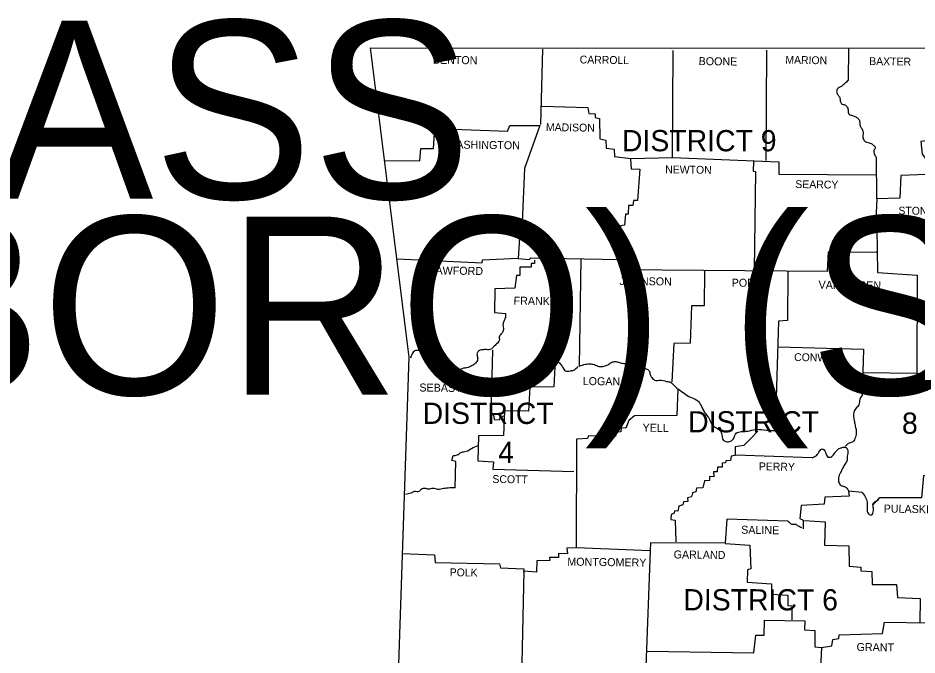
# Model space of a CAD drawing. Extents: x 309348 to 309445, y 336383 to 336484.
# Drawn here: x 309371.203 to 309375.728, y 336399.208 to 336402.416 of the extents above; entities that cross this region are included whole.
import ezdxf

# ---------------------------------------------------------------- set-up
doc = ezdxf.new("R2010")
doc.units = 0
doc.layers.add('R_Annotation', color=7, linetype='Continuous')

msp = doc.modelspace()

# ---------------------------------------------------------------- linework, layer by layer
at = {"layer": 'R_Annotation'}
msp.add_line((309375.5062, 336399.965), (309375.5401, 336399.9989), dxfattribs=at)
for points in [[(309372.9764, 336402.2658), (309374.4937, 336402.2641), (309375.8252, 336402.2663), (309377.396, 336402.29), (309378.1242, 336402.3065)], [(309372.9764, 336402.2658), (309373.1698, 336400.7078), (309373.0841, 336398.1647)], [(309373.8425, 336402.2597), (309373.8338, 336401.8801)], [(309373.8405, 336401.9729), (309374.0713, 336401.9653), (309374.0769, 336401.9353), (309374.1088, 336401.9343), (309374.1079, 336401.9156), (309374.1304, 336401.91), (309374.1322, 336401.8078), (309374.1613, 336401.8012), (309374.1631, 336401.7609), (309374.2044, 336401.7553), (309374.2063, 336401.7178), (309374.2879, 336401.7093), (309374.4981, 336401.7139), (309374.5003, 336402.2529)], [(309374.9704, 336402.2545), (309374.9673, 336401.6977)], [(309375.3832, 336402.2609), (309375.3813, 336402.1006)], [(309375.8252, 336402.2607), (309375.827, 336402.0376), (309375.811, 336402.0367), (309375.8137, 336401.8033), (309375.748, 336401.7939), (309375.7536, 336401.7311), (309375.7761, 336401.7021), (309375.7742, 336401.628), (309375.6466, 336401.6234), (309375.6418, 336401.509), (309375.5255, 336401.5053), (309375.5198, 336401.3666), (309375.5263, 336401.3553), (309375.529, 336401.1341), (309375.7298, 336401.1209), (309375.7268, 336400.6269), (309375.8863, 336400.6221), (309375.886, 336400.1197), (309375.7603, 336400.1104), (309375.7509, 336399.9998), (309375.5397, 336399.9989)], [(309373.0502, 336401.6986), (309373.2257, 336401.6976), (309373.2304, 336401.7595), (309373.2952, 336401.7594), (309373.3008, 336401.8597), (309373.6668, 336401.8464), (309373.6781, 336401.8746), (309373.8291, 336401.8754), (309373.753, 336401.658), (309373.7378, 336401.3102), (309373.7266, 336401.3093), (309373.7209, 336401.2043), (309373.7763, 336401.1996), (309373.7847, 336401.208), (309374.2323, 336401.1994), (309374.237, 336401.1497)], [(309374.286, 336401.7074), (309374.2898, 336401.6568), (309374.3329, 336401.654), (309374.3216, 336401.4965), (309374.3019, 336401.4974), (309374.2981, 336401.4721), (309374.2756, 336401.4721), (309374.2746, 336401.429), (309374.2606, 336401.4281), (309374.2558, 336401.3728), (309374.2352, 336401.37), (309374.2323, 336401.2856), (309374.2417, 336401.2791), (309374.2323, 336401.1994)], [(309374.4981, 336401.7139), (309375.0329, 336401.6911), (309375.032, 336401.6302), (309375.5227, 336401.6262)], [(309375.5255, 336401.5053), (309375.5247, 336401.7162)], [(309374.9044, 336401.694), (309374.9034, 336401.6453), (309374.9156, 336401.6425), (309374.9079, 336401.1475)], [(309374.237, 336401.1497), (309375.2785, 336401.1408), (309375.2833, 336401.2392), (309375.5253, 336401.2363)], [(309375.5225, 336401.2372), (309375.5253, 336401.24)], [(309373.1119, 336401.2037), (309373.5388, 336401.1838), (309373.5407, 336401.1988), (309373.719, 336401.2071)], [(309373.8035, 336401.1958), (309373.8035, 336401.179), (309373.7856, 336401.179), (309373.7866, 336401.1621), (309373.7293, 336401.1612), (309373.7284, 336401.119), (309373.7124, 336401.119), (309373.7039, 336401.0562), (309373.6026, 336401.0516), (309373.6016, 336400.9325), (309373.656, 336400.9288)], [(309374.0352, 336401.2032), (309374.0284, 336400.6624)], [(309374.6583, 336401.142), (309374.6572, 336400.9667), (309374.5925, 336400.9658), (309374.5868, 336400.7793), (309374.5042, 336400.7765), (309374.4947, 336400.5834)], [(309375.0786, 336401.1371), (309375.0766, 336400.8934), (309375.0316, 336400.8897), (309375.0135, 336400.3385)], [(309375.0297, 336400.7594), (309375.4585, 336400.7489), (309375.4527, 336400.5174)], [(309373.5921, 336400.7432), (309373.5826, 336400.4207), (309373.5966, 336400.417), (309373.5994, 336400.3945), (309373.6276, 336400.3926), (309373.6304, 336400.4085), (309373.6529, 336400.4123)], [(309373.9074, 336400.6924), (309373.9007, 336400.5584), (309373.7787, 336400.5575), (309373.7721, 336400.4356), (309373.6511, 336400.4385), (309373.6472, 336400.3129), (309373.5206, 336400.312), (309373.5167, 336400.1864), (309373.5965, 336400.1817), (309373.5937, 336400.1433), (309374.0009, 336400.1318)], [(309375.4537, 336400.6308), (309375.7268, 336400.6269)], [(309374.5238, 336400.5487), (309374.52, 336400.4137), (309374.306, 336400.4129), (309374.2778, 336400.3885), (309374.2619, 336400.351), (309374.2384, 336400.3529), (309374.2375, 336400.3314), (309374.2103, 336400.3286), (309374.2112, 336400.3089), (309374.0751, 336400.3127), (309374.0704, 336400.2977), (309374.0141, 336400.2959), (309374.012, 336399.7475), (309373.9651, 336399.7466), (309373.9688, 336399.7185), (309373.9238, 336399.7194), (309373.9228, 336399.6988), (309373.8787, 336399.6988), (309373.8796, 336399.6838), (309373.8139, 336399.682), (309373.813, 336399.6248), (309373.7492, 336399.6304), (309373.7386, 336399.1693)], [(309374.9262, 336400.3348), (309374.8924, 336400.2983), (309374.8558, 336400.2636), (309374.8136, 336400.2571), (309374.8136, 336400.213), (309374.7929, 336400.2102), (309374.7891, 336400.1877), (309374.7657, 336400.1858), (309374.7638, 336400.1755), (309374.7479, 336400.1746), (309374.7469, 336400.1549), (309374.7244, 336400.154), (309374.7225, 336400.1315), (309374.7037, 336400.1315), (309374.7047, 336400.1053), (309374.684, 336400.1071), (309374.6831, 336400.0865), (309374.6577, 336400.0847), (309374.6502, 336400.0509), (309374.6183, 336400.0481), (309374.6155, 336400.0294), (309374.5986, 336400.0247), (309374.5939, 336400.005), (309374.5723, 336400.0003), (309374.5742, 336399.9806), (309374.5526, 336399.9788), (309374.5488, 336399.9638), (309374.5291, 336399.9582), (309374.5244, 336399.9329), (309374.5094, 336399.9338), (309374.5047, 336399.9207), (309374.4906, 336399.916), (309374.4897, 336399.8907), (309374.5112, 336399.8869), (309374.5149, 336399.7782)], [(309373.4031, 336400.0505), (309373.406, 336400.1827), (309373.3873, 336400.1883), (309373.3929, 336400.2137)], [(309375.2011, 336400.2016), (309374.8145, 336400.2139)], [(309375.4515, 336400.0262), (309375.384, 336400.0337), (309375.3868, 336400.0084), (309375.2639, 336400.0038), (309375.2601, 336399.9672), (309375.1447, 336399.9607), (309375.1381, 336399.8951), (309375.1549, 336399.8866), (309375.1549, 336399.8435)], [(309375.078, 336399.8829), (309374.7712, 336399.8924), (309374.7627, 336399.7715), (309374.3873, 336399.7736), (309374.3854, 336399.7333)], [(309375.1615, 336399.8857), (309375.2666, 336399.8791), (309375.2628, 336399.7619), (309375.3857, 336399.7572), (309375.3875, 336399.655), (309375.4457, 336399.6503), (309375.4457, 336399.6325), (309375.5001, 336399.6287), (309375.502, 336399.5631), (309375.6258, 336399.563), (309375.6295, 336399.4983), (309375.744, 336399.4927), (309375.743, 336399.3708)], [(309374.7626, 336399.7705), (309374.8875, 336399.7612), (309374.8911, 336399.643), (309374.8752, 336399.6374), (309374.8733, 336399.5746), (309374.9962, 336399.5661), (309374.9962, 336399.5146), (309375.0778, 336399.5098), (309375.0787, 336399.4583), (309375.0984, 336399.4555), (309375.0974, 336399.3861)], [(309373.1365, 336399.7188), (309373.2988, 336399.7131), (309373.3025, 336399.6738), (309373.6272, 336399.6671), (309373.631, 336399.6464), (309373.7492, 336399.6426), (309373.7482, 336399.6248)], [(309374.3854, 336399.7333), (309374.012, 336399.7475)], [(309374.3854, 336399.7333), (309374.3635, 336399.1493)], [(309374.3702, 336399.2271), (309374.9069, 336399.2193), (309374.9172, 336399.3084), (309374.9595, 336399.3084), (309374.9604, 336399.3834), (309375.1631, 336399.3805), (309375.1612, 336399.3355), (309375.2138, 336399.3317), (309375.2137, 336399.2492), (309375.2475, 336399.2464)], [(309375.2475, 336399.2464), (309375.3001, 336399.2538), (309375.3038, 336399.2857), (309375.3348, 336399.2913), (309375.3367, 336399.3101), (309375.5553, 336399.3165), (309375.5638, 336399.3737), (309375.7881, 336399.3699)], [(309375.2475, 336399.2464), (309375.2361, 336399.0008), (309375.2277, 336399.0036), (309375.2286, 336398.8761)]]:
    msp.add_lwpolyline(points, dxfattribs=at)
for points in [[(309375.3813, 336402.1006), (309375.3644, 336402.0866), (309375.3494, 336402.0735), (309375.3268, 336402.0575), (309375.324, 336402.0425), (309375.3315, 336402.0275), (309375.339, 336402.0153), (309375.3418, 336401.9985), (309375.3484, 336401.9844), (309375.3643, 336401.9788), (309375.3775, 336401.9666), (309375.3821, 336401.9497), (309375.384, 336401.9338), (309375.399, 336401.9263), (309375.4159, 336401.9206), (309375.4319, 336401.9094), (309375.4394, 336401.8953), (309375.4412, 336401.8775), (309375.4478, 336401.8634), (309375.4553, 336401.8466), (309375.4572, 336401.8325), (309375.4553, 336401.8184), (309375.459, 336401.8053), (309375.4712, 336401.7922), (309375.4928, 336401.7856), (309375.5078, 336401.7762), (309375.5181, 336401.7631), (309375.5115, 336401.7472), (309375.5125, 336401.7331), (309375.5209, 336401.7162)], [(309373.656, 336400.9288), (309373.656, 336400.9091), (309373.6485, 336400.8884), (309373.6438, 336400.8706), (309373.6466, 336400.8472), (309373.6381, 336400.8285), (309373.6259, 336400.8135), (309373.6259, 336400.7947), (309373.6118, 336400.775), (309373.5968, 336400.76), (309373.5837, 336400.7479), (309373.5602, 336400.746), (309373.5405, 336400.7451), (309373.5208, 336400.7385), (309373.5133, 336400.7245), (309373.517, 336400.7029), (309373.5095, 336400.6823), (309373.4898, 336400.6664), (309373.4682, 336400.6561), (309373.4457, 336400.6523), (309373.4147, 336400.6373), (309373.3865, 336400.6252), (309373.3565, 336400.6271), (309373.3284, 336400.6393), (309373.303, 336400.6505), (309373.2833, 336400.6618), (309373.2674, 336400.6965), (309373.2571, 336400.7152), (309373.2393, 336400.734), (309373.2177, 336400.7415), (309373.1999, 336400.7396), (309373.1783, 336400.7031)], [(309373.9074, 336400.6924), (309373.928, 336400.6793), (309373.9439, 336400.6577), (309373.958, 336400.6399), (309373.9815, 336400.639), (309374.0002, 336400.6427), (309374.0218, 336400.6614)], [(309374.0284, 336400.6624), (309374.0594, 336400.6727), (309374.0819, 336400.6745), (309374.1044, 336400.6708), (309374.1279, 336400.6614), (309374.1532, 336400.6632), (309374.172, 336400.6698), (309374.1907, 336400.682), (309374.2114, 336400.6857), (309374.2311, 336400.682), (309374.2517, 336400.6763), (309374.2742, 336400.6829), (309374.2874, 336400.6951), (309374.3099, 336400.6988), (309374.3296, 336400.6988), (309374.3437, 336400.6828), (309374.3465, 336400.666), (309374.3643, 336400.65), (309374.3803, 336400.6397), (309374.3849, 336400.62), (309374.3934, 336400.606), (309374.4018, 336400.5966), (309374.414, 336400.5909), (309374.4347, 336400.5928), (309374.4666, 336400.5862), (309374.4872, 336400.5815), (309374.506, 336400.5656), (309374.5238, 336400.5487)], [(309374.5238, 336400.5487), (309374.5566, 336400.5262), (309374.5876, 336400.5065), (309374.6195, 336400.4924), (309374.6373, 336400.4718), (309374.6532, 336400.4399), (309374.6663, 336400.4202), (309374.6832, 336400.3959), (309374.6954, 336400.3687), (309374.7151, 336400.3537), (309374.7357, 336400.3405), (309374.746, 336400.3171), (309374.7507, 336400.2936), (309374.7732, 336400.2824), (309374.7948, 336400.2871), (309374.807, 336400.3011), (309374.8183, 336400.3255), (309374.8436, 336400.333), (309374.8765, 336400.3358), (309374.914, 336400.3442), (309374.9553, 336400.3423), (309375.0135, 336400.3385)], [(309375.4527, 336400.5174), (309375.4405, 336400.4958), (309375.4349, 336400.4677), (309375.4198, 336400.4499), (309375.4105, 336400.4293), (309375.4095, 336400.4021), (309375.4142, 336400.3777), (309375.4189, 336400.3543), (309375.4226, 336400.3327), (309375.4179, 336400.3055), (309375.4057, 336400.2821), (309375.3869, 336400.2755), (309375.3691, 336400.2596)], [(309373.3929, 336400.2137), (309373.4135, 336400.2155), (309373.4333, 336400.2286), (309373.4595, 336400.2342), (309373.4858, 336400.2483), (309373.5187, 336400.2633)], [(309375.2011, 336400.2016), (309375.2245, 336400.2147), (309375.2368, 336400.2344), (309375.2518, 336400.2465), (309375.2668, 336400.2297), (309375.2799, 336400.2053), (309375.294, 336400.2053), (309375.3118, 336400.2221), (309375.3231, 336400.2371), (309375.3372, 336400.2484), (309375.3522, 336400.2531), (309375.3681, 336400.2549), (309375.3803, 336400.2371), (309375.3766, 336400.209), (309375.3765, 336400.1902), (309375.3662, 336400.1706), (309375.3549, 336400.15), (309375.3427, 336400.1265), (309375.3333, 336400.1012), (309375.3352, 336400.0768), (309375.3483, 336400.0609), (309375.3633, 336400.0562), (309375.384, 336400.0356)], [(309373.4031, 336400.0505), (309373.3759, 336400.0496), (309373.345, 336400.0459), (309373.3168, 336400.0421), (309373.2915, 336400.0468), (309373.268, 336400.0431), (309373.2521, 336400.0469), (309373.2324, 336400.0422), (309373.2211, 336400.0309), (309373.1976, 336400.031), (309373.1807, 336400.0235), (309373.1535, 336400.0169)], [(309375.4515, 336400.0262), (309375.4675, 336400.0055), (309375.4768, 336399.9774), (309375.4768, 336399.9455), (309375.4843, 336399.9193), (309375.4993, 336399.9137), (309375.5087, 336399.9362), (309375.5069, 336399.9587), (309375.5069, 336399.9718), (309375.5228, 336399.983), (309375.5397, 336399.9989)], [(309375.1484, 336399.8482), (309375.1305, 336399.8576), (309375.1165, 336399.866), (309375.1014, 336399.8651), (309375.0893, 336399.8726), (309375.078, 336399.8829)]]:
    msp.add_spline(points, degree=3, dxfattribs=at)

# ---------------------------------------------------------------- texts
for s, p in [('HWY. 351 RR OVERPASS', (309359.0212, 336401.5059)), ('(AIRPORT RD.) (JONESBORO) (S)', (309357.2627, 336400.5194))]:
    msp.add_text(s, height=0.896903, dxfattribs=at).set_placement(p)
for s, height, rotation, p in [('BENTON', 0.04031, 359.2273, (309373.2907, 336402.1859)), ('CARROLL', 0.03937, 359.1227, (309374.0301, 336402.1875)), ('BOONE', 0.04031, 359.3745, (309374.6288, 336402.1788)), ('MARION', 0.03937, 359.16, (309375.0651, 336402.1861)), ('BAXTER', 0.03937, 359.2305, (309375.4874, 336402.1793)), ('MADISON', 0.03937, 359.0653, (309373.8601, 336401.8473)), ('DISTRICT 9', 0.10686, 359.9738, (309374.2432, 336401.7451)), ('WASHINGTON', 0.0403, 359.2066, (309373.358, 336401.7594)), ('NEWTON', 0.03937, 359.2462, (309374.4605, 336401.6342)), ('SEARCY', 0.03936, 359.2273, (309375.1155, 336401.5599)), ('STONE', 0.03936, 359.3745, (309375.6343, 336401.4265)), ('CRAWFORD', 0.0403, 359.2516, (309373.2263, 336401.1258)), ('JOHNSON', 0.04031, 359.3259, (309374.2303, 336401.0719)), ('POPE', 0.04031, 359.5897, (309374.7952, 336401.0632)), ('VAN BUREN', 0.04031, 359.3252, (309375.2325, 336401.0527)), ('FRANKLIN', 0.04031, 359.1562, (309373.6973, 336400.9728)), ('CONWAY', 0.03936, 359.0119, (309375.1094, 336400.6891)), ('SEBASTIAN', 0.0403, 359.2561, (309373.2232, 336400.5353)), ('LOGAN', 0.04031, 359.3713, (309374.0452, 336400.5677)), ('FAULKNER', 0.03937, 359.2232, (309375.5053, 336400.5408)), ('DISTRICT', 0.10686, 359.9738, (309373.24, 336400.3721)), ('DISTRICT', 0.10686, 359.9738, (309374.5762, 336400.3293)), ('8', 0.1069, 359.9738, (309375.6525, 336400.3223)), ('YELL', 0.04031, 359.1733, (309374.3463, 336400.3332)), ('4', 0.1069, 359.9738, (309373.62, 336400.1751)), ('PERRY', 0.03937, 359.0605, (309374.9317, 336400.1389)), ('SCOTT', 0.03937, 359.3807, (309373.5908, 336400.0748)), ('PULASKI', 0.04031, 359.0278, (309375.5603, 336399.9258)), ('SALINE', 0.04031, 359.1238, (309374.8429, 336399.8191)), ('GARLAND', 0.04031, 359.3402, (309374.503, 336399.6947)), ('MONTGOMERY', 0.04031, 359.2689, (309373.9678, 336399.6585)), ('POLK', 0.03936, 359.1898, (309373.3757, 336399.6053)), ('DISTRICT 6', 0.10686, 359.9738, (309374.5522, 336399.4331)), ('GRANT', 0.04031, 359.3776, (309375.4239, 336399.2285))]:
    msp.add_text(s, height=height, rotation=rotation, dxfattribs=at).set_placement(p)

doc.saveas('drawing.dxf')
